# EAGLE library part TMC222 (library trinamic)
Micro Stepping Stepper Motor Controller / Driver with Two Wire Serial Interface
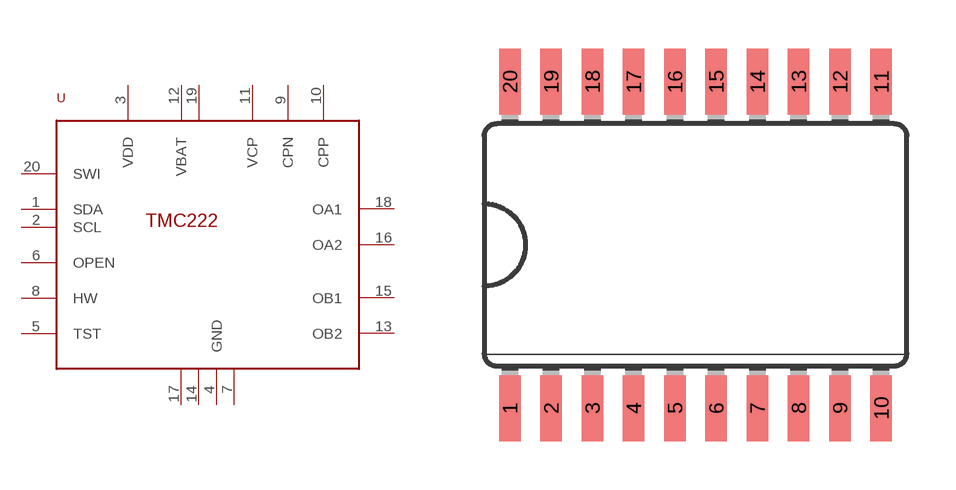
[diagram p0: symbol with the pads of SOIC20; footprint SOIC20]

Designator prefix -

## TMC222  [SOIC20]
1  SDA
2  SCL
3  VDD
4  GND
5  TST
6  OPEN
7  GND2
8  HW
9  CPN
10  CPP
11  VCP
12  VBAT
13  OB2
14  GND3
15  OB1
16  OA2
17  GND4
18  OA1
19  VBAT2
20  SWI

## Footprint SOIC20 (pad centres in mm)
SOIC 20 (Wide)
smd 0.66 x 2.032: 1 -5.715,-5.029; 2 -4.445,-5.029; 3 -3.175,-5.029; 4 -1.905,-5.029; 5 -0.635,-5.029; 6 0.635,-5.029; 7 1.905,-5.029; 8 3.175,-5.029; 9 4.445,-5.029; 10 5.715,-5.029; 11 5.715,5.029; 12 4.445,5.029; 13 3.175,5.029; 14 1.905,5.029; 15 0.635,5.029; 16 -0.635,5.029; 17 -1.905,5.029; 18 -3.175,5.029; 19 -4.445,5.029; 20 -5.715,5.029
